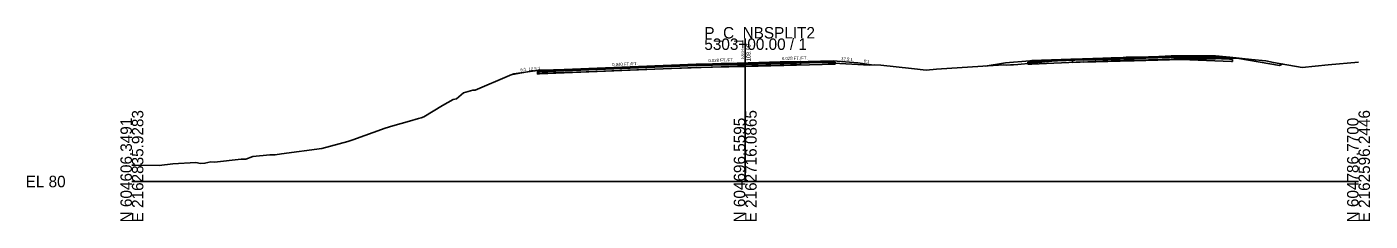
# Model space of a CAD drawing. Extents: x -26 to 1303, y -10 to 12038.
# Drawn here: x -25.7 to 302.8, y 11990.3 to 12037.8 of the extents above; entities that cross this region are included whole.
import ezdxf

# ---------------------------------------------------------------- set-up
doc = ezdxf.new("R2010")
doc.units = 0
for name, color, linetype in [('RD_GPK_XS_Cell', 7, 'Continuous'), ('RD_XS_Base', 7, 'Continuous'), ('RD_XS_ExGround', 7, 'Continuous'), ('RD_XS_ExPaveRet', 7, 'Continuous'), ('RD_XS_Greenside', 7, 'Continuous'), ('RD_XS_Pave', 7, 'Continuous'), ('RD_XS_PaveOvlay_CP', 7, 'Continuous'), ('RD_XS_TieSlope', 7, 'Continuous'), ('RD_XS_TX_Elev_EX', 7, 'Continuous'), ('RD_XS_TX_Elev_PR', 7, 'Continuous'), ('RD_XS_TX_ShdSlope', 7, 'Continuous'), ('RD_XS_TX_Slope', 7, 'Continuous')]:
    doc.layers.add(name, color=color, linetype=linetype)

msp = doc.modelspace()

# ---------------------------------------------------------------- linework, layer by layer
at = {"layer": 'RD_GPK_XS_Cell'}
for p, q in [((150, 12000), (150, 12035)), ((0, 12000), (150, 12000)), ((150, 12000), (300, 12000))]:
    msp.add_line(p, q, dxfattribs=at)
at = {"layer": 'RD_XS_Base'}
for p, q in [((138, 12028.36), (99.67, 12026.82)), ((99.67, 12026.32), (138, 12027.86)), ((150, 12028.67), (138, 12028.36)), ((138, 12028.36), (138, 12028.36)), ((138, 12027.86), (150, 12028.17)), ((138, 12027.86), (138, 12027.86)), ((150, 12028.67), (172.02, 12029.24)), ((150, 12028.17), (150, 12028.83)), ((150, 12028.83), (150, 12028.83)), ((150, 12028.83), (150, 12028.83)), ((150, 12028.83), (150, 12028.67)), ((172.02, 12028.74), (150, 12028.17)), ((150, 12028.67), (150, 12028.67)), ((150, 12028.17), (150, 12028.67)), ((150, 12028.67), (150, 12028.67)), ((150, 12028.67), (150, 12028.67)), ((150, 12028.17), (150, 12028.17)), ((171.52, 12029.23), (171.52, 12029.23)), ((172.02, 12029.24), (172.02, 12028.74)), ((172.02, 12029.21), (172.02, 12029.21)), ((219.17, 12029.21), (219.15, 12029.21)), ((219.15, 12029.21), (219.15, 12028.73)), ((219.15, 12028.73), (219.15, 12028.71)), ((219.15, 12028.71), (219.17, 12028.71)), ((219.65, 12029.23), (219.17, 12029.21)), ((219.17, 12028.71), (219.65, 12028.73)), ((220.13, 12029.25), (219.65, 12029.23)), ((219.65, 12028.73), (220.13, 12028.75)), ((232.7, 12029.75), (220.13, 12029.25)), ((220.13, 12028.75), (232.7, 12029.25)), ((244.7, 12030.05), (232.7, 12029.71)), ((232.7, 12029.21), (244.7, 12029.55)), ((244.7, 12030.06), (244.7, 12030.21)), ((244.7, 12030.21), (244.7, 12029.57)), ((244.7, 12030.05), (244.7, 12030.06)), ((245.11, 12030.06), (244.7, 12030.05)), ((244.7, 12030.05), (244.7, 12030.05)), ((244.7, 12030.05), (244.7, 12030.05)), ((244.7, 12029.57), (244.7, 12030.05)), ((244.7, 12029.57), (244.7, 12029.55)), ((244.7, 12029.55), (244.7, 12029.57)), ((244.7, 12029.55), (245.11, 12029.56)), ((256.7, 12030.39), (245.11, 12030.06)), ((245.11, 12029.56), (256.7, 12029.89)), ((268.42, 12029.92), (256.7, 12030.39)), ((256.7, 12029.89), (268.91, 12029.4)), ((268.7, 12029.91), (268.42, 12029.92)), ((269.19, 12029.89), (268.7, 12029.91)), ((268.91, 12029.4), (269.2, 12029.39)), ((269.2, 12029.89), (269.19, 12029.89)), ((269.2, 12029.4), (269.2, 12029.89)), ((269.2, 12029.39), (269.2, 12029.4)), ((99.67, 12026.82), (99.17, 12026.8)), ((99.17, 12026.8), (99.17, 12026.8)), ((99.17, 12026.8), (99.17, 12026.3)), ((99.17, 12026.3), (99.67, 12026.32)), ((99.67, 12026.82), (99.67, 12026.82)), ((99.67, 12026.32), (99.67, 12026.32))]:
    msp.add_line(p, q, dxfattribs=at)
at = {"layer": 'RD_XS_ExGround'}
msp.add_lwpolyline([(0, 12004.02), (0.8, 12004.02), (6.64, 12003.95), (10.01, 12004.29), (15.6, 12004.64), (16.74, 12004.44), (17.85, 12004.47), (19.27, 12004.8), (20.22, 12004.77), (26.73, 12005.51), (27.9, 12005.49), (29.61, 12006.12), (33.77, 12006.51), (35.07, 12006.5), (36.55, 12006.74), (46.41, 12008.11), (52.78, 12009.81), (54.05, 12010.17), (61.97, 12013.04), (63.85, 12013.65), (67.85, 12014.75), (70.1, 12015.38), (70.76, 12015.61), (71.36, 12015.86), (76, 12018.63), (78.61, 12020.1), (79.4, 12020.24), (81.13, 12021.73), (83.34, 12022.33), (83.99, 12022.34), (92.34, 12025.9), (92.53, 12025.99), (93.39, 12026.35), (99.09, 12027.16), (99.29, 12027.2), (99.41, 12027.21), (100.3, 12027.23), (108.76, 12027.48), (113.45, 12027.68), (121.26, 12027.99), (129.95, 12028.35), (134.09, 12028.49), (134.44, 12028.51), (136.77, 12028.59), (144.11, 12028.84), (148.09, 12028.99), (158.52, 12029.25), (163.52, 12029.38), (167.74, 12029.15), (168.86, 12029.09), (180.36, 12028.5), (181.59, 12028.52), (183.18, 12028.46), (190.7, 12027.63), (194.28, 12027.25), (196.82, 12027.51), (213.2, 12028.52), (213.82, 12028.5), (214.86, 12028.52), (215.64, 12028.53), (216.64, 12028.62), (230.04, 12029.91), (240.12, 12030.29), (242.47, 12030.37), (244.95, 12030.44), (245.4, 12030.45), (247.57, 12030.45), (248.77, 12030.49), (249.24, 12030.5), (249.54, 12030.51), (249.72, 12030.54), (254.85, 12030.74), (261.42, 12030.76), (265, 12030.78), (268.54, 12030.42), (273.82, 12029.87), (277.36, 12029.5), (279.22, 12029.16), (286.24, 12027.93), (292.61, 12028.53), (300, 12029.24)], dxfattribs=at)
at = {"layer": 'RD_XS_ExPaveRet'}
for points in [[(163.52, 12029.38), (163.52, 12029.38), (163.52, 12029.38), (163.52, 12028.63), (163.52, 12028.63), (158.52, 12028.5), (158.52, 12028.5), (148.09, 12028.24), (148.09, 12028.24), (144.11, 12028.09), (144.11, 12028.09), (136.77, 12027.84), (136.77, 12027.84), (134.44, 12027.76), (134.09, 12027.74), (134.09, 12027.74), (129.95, 12027.6), (129.95, 12027.6), (129.95, 12027.6), (121.26, 12027.24), (121.26, 12027.24), (113.45, 12026.93), (113.45, 12026.93), (108.76, 12026.73), (100.3, 12026.48), (100.3, 12026.48), (99.41, 12026.46), (99.29, 12026.45), (99.29, 12026.45), (99.29, 12027.2), (99.29, 12027.2), (99.29, 12027.2), (99.41, 12027.21), (100.3, 12027.23), (100.3, 12027.23), (108.76, 12027.48), (113.45, 12027.68), (113.45, 12027.68), (121.26, 12027.99), (121.26, 12027.99), (129.95, 12028.35), (129.95, 12028.35), (129.95, 12028.35), (134.09, 12028.49), (134.09, 12028.49), (134.44, 12028.51), (136.77, 12028.59), (136.77, 12028.59), (144.11, 12028.84), (144.11, 12028.84), (148.09, 12028.99), (148.09, 12028.99), (158.52, 12029.25), (158.52, 12029.25), (163.52, 12029.38)], [(158.52, 12029.25), (148.09, 12028.99), (144.11, 12028.84), (136.77, 12028.59), (134.44, 12028.51), (134.09, 12028.49), (129.95, 12028.35), (121.26, 12027.99), (113.45, 12027.68), (108.76, 12027.48), (100.3, 12027.23), (99.41, 12027.21), (99.29, 12027.2), (99.29, 12026.45), (99.41, 12026.46), (100.3, 12026.48), (108.76, 12026.73), (113.45, 12026.93), (121.26, 12027.24), (129.95, 12027.6), (134.09, 12027.74), (134.44, 12027.76), (136.77, 12027.84), (144.11, 12028.09), (148.09, 12028.24), (158.52, 12028.5), (163.52, 12028.63), (163.52, 12029.38), (158.52, 12029.25)], [(265, 12030.78), (263.03, 12030.77), (261.42, 12030.76), (255.7, 12030.74), (254.85, 12030.74), (254.19, 12030.72), (249.72, 12030.54), (249.59, 12030.52), (249.36, 12030.51), (249.32, 12030.51), (249.25, 12030.51), (249.17, 12030.5), (248.77, 12030.49), (248.61, 12030.49), (247.57, 12030.45), (246.93, 12030.45), (245.4, 12030.45), (245.08, 12030.44), (244.95, 12030.44), (243.18, 12030.39), (242.62, 12030.37), (239.98, 12030.28), (239.51, 12030.26), (237.48, 12030.19), (230.04, 12029.91), (230.04, 12029.91), (230.04, 12029.76), (230.04, 12029.16), (230.04, 12029.16), (237.48, 12029.44), (239.51, 12029.51), (239.98, 12029.53), (242.62, 12029.62), (243.18, 12029.64), (244.95, 12029.69), (245.08, 12029.69), (245.4, 12029.7), (246.93, 12029.7), (247.57, 12029.7), (248.61, 12029.74), (248.77, 12029.74), (249.17, 12029.75), (249.25, 12029.76), (249.32, 12029.76), (249.36, 12029.76), (249.59, 12029.77), (249.72, 12029.79), (254.19, 12029.97), (254.85, 12029.99), (255.7, 12029.99), (261.42, 12030.01), (263.03, 12030.02), (265, 12030.03), (265, 12030.03), (265, 12030.03), (265, 12030.61), (265, 12030.78), (265, 12030.78), (265, 12030.78)], [(265, 12030.78), (263.03, 12030.77), (261.42, 12030.76), (255.7, 12030.74), (254.85, 12030.74), (254.19, 12030.72), (249.72, 12030.54), (249.59, 12030.52), (249.36, 12030.51), (249.32, 12030.51), (249.25, 12030.51), (249.17, 12030.5), (248.77, 12030.49), (248.61, 12030.49), (247.57, 12030.45), (246.93, 12030.45), (245.4, 12030.45), (245.08, 12030.44), (244.95, 12030.44), (243.18, 12030.39), (242.62, 12030.37), (239.98, 12030.28), (239.51, 12030.26), (237.48, 12030.19), (230.04, 12029.91), (230.04, 12029.76), (230.04, 12029.16), (237.48, 12029.44), (239.51, 12029.51), (239.98, 12029.53), (242.62, 12029.62), (243.18, 12029.64), (244.95, 12029.69), (245.08, 12029.69), (245.4, 12029.7), (246.93, 12029.7), (247.57, 12029.7), (248.61, 12029.74), (248.77, 12029.74), (249.17, 12029.75), (249.25, 12029.76), (249.32, 12029.76), (249.36, 12029.76), (249.59, 12029.77), (249.72, 12029.79), (254.19, 12029.97), (254.85, 12029.99), (255.7, 12029.99), (261.42, 12030.01), (263.03, 12030.02), (265, 12030.03), (265, 12030.03), (265, 12030.61), (265, 12030.78), (265, 12030.78)]]:
    msp.add_lwpolyline(points, dxfattribs=at)
at = {"layer": 'RD_XS_Greenside'}
for p, q in [((177.52, 12029.07), (180.88, 12028.51)), ((213.65, 12029.07), (208.68, 12028.24)), ((270.7, 12030.07), (280.7, 12028.4)), ((280.7, 12028.4), (281.45, 12028.77)), ((97.67, 12026.98), (93.07, 12026.21))]:
    msp.add_line(p, q, dxfattribs=at)
at = {"layer": 'RD_XS_Pave'}
for p, q in [((138, 12028.68), (99.67, 12027.14)), ((99.67, 12026.98), (138, 12028.52)), ((138, 12028.52), (99.67, 12026.98)), ((99.67, 12026.82), (138, 12028.36)), ((150, 12028.99), (138, 12028.68)), ((138, 12028.52), (150, 12028.83)), ((150, 12028.83), (138, 12028.52)), ((138, 12028.68), (138, 12028.68)), ((138, 12028.36), (150, 12028.67)), ((138, 12028.52), (138, 12028.52)), ((138, 12028.52), (138, 12028.52)), ((138, 12028.36), (138, 12028.36)), ((171.52, 12029.55), (150, 12028.99)), ((171.52, 12029.39), (150, 12028.83)), ((150, 12028.83), (171.52, 12029.39)), ((150, 12028.67), (171.52, 12029.23)), ((150, 12028.99), (150, 12028.99)), ((150, 12028.83), (150, 12028.83)), ((150, 12028.83), (150, 12028.83)), ((150, 12028.83), (150, 12028.67)), ((150, 12028.83), (150, 12028.83)), ((150, 12028.67), (150, 12028.83)), ((150, 12028.83), (150, 12028.83)), ((150, 12028.83), (150, 12028.83)), ((150, 12028.67), (150, 12028.67)), ((150, 12028.67), (150, 12028.67)), ((171.52, 12029.39), (171.52, 12029.55)), ((171.52, 12029.55), (171.52, 12029.55)), ((171.52, 12029.23), (171.52, 12029.39)), ((171.52, 12029.39), (171.52, 12029.39)), ((220.13, 12029.57), (219.65, 12029.55)), ((219.65, 12029.55), (219.65, 12029.4)), ((220.13, 12029.41), (219.65, 12029.39)), ((219.65, 12029.39), (220.13, 12029.41)), ((219.65, 12029.4), (219.65, 12029.39)), ((219.65, 12029.39), (219.65, 12029.24)), ((219.65, 12029.23), (220.13, 12029.25)), ((219.65, 12029.24), (219.65, 12029.23)), ((229.65, 12029.95), (220.13, 12029.57)), ((232.7, 12029.91), (220.13, 12029.41)), ((220.13, 12029.41), (232.7, 12029.91)), ((220.13, 12029.25), (232.7, 12029.75)), ((232.7, 12030.03), (229.65, 12029.95)), ((244.7, 12030.37), (232.7, 12030.03)), ((244.7, 12030.21), (232.7, 12029.87)), ((232.7, 12029.87), (244.7, 12030.21)), ((232.7, 12029.71), (244.7, 12030.05)), ((245.11, 12030.38), (244.7, 12030.37)), ((245.11, 12030.22), (244.7, 12030.21)), ((244.7, 12030.21), (245.11, 12030.22)), ((244.7, 12030.06), (244.7, 12030.21)), ((244.7, 12030.21), (244.7, 12030.21)), ((244.7, 12030.21), (244.7, 12030.21)), ((244.7, 12030.21), (244.7, 12030.06)), ((244.7, 12030.05), (244.7, 12030.06)), ((244.7, 12030.06), (244.7, 12030.05)), ((244.7, 12030.05), (245.11, 12030.06)), ((244.7, 12030.05), (244.7, 12030.05)), ((244.7, 12030.05), (244.7, 12030.05)), ((256.7, 12030.7), (245.11, 12030.38)), ((256.7, 12030.55), (245.11, 12030.22)), ((245.11, 12030.22), (256.7, 12030.55)), ((245.11, 12030.06), (256.7, 12030.39)), ((268.42, 12030.24), (256.7, 12030.7)), ((268.42, 12030.08), (256.7, 12030.55)), ((256.7, 12030.55), (268.42, 12030.08)), ((256.7, 12030.39), (268.42, 12029.92)), ((268.7, 12030.22), (268.42, 12030.24)), ((268.7, 12030.07), (268.42, 12030.08)), ((268.42, 12030.08), (268.7, 12030.07)), ((268.42, 12029.92), (268.7, 12029.91)), ((268.7, 12030.07), (268.7, 12030.22)), ((268.7, 12029.91), (268.7, 12030.07)), ((268.7, 12030.07), (268.7, 12030.07)), ((268.7, 12029.91), (268.7, 12029.91)), ((99.67, 12027.14), (99.67, 12027.14)), ((99.67, 12027.14), (99.67, 12026.98)), ((99.67, 12026.98), (99.67, 12026.98)), ((99.67, 12026.98), (99.67, 12026.82))]:
    msp.add_line(p, q, dxfattribs=at)
at = {"layer": 'RD_XS_PaveOvlay_CP'}
for p, q in [((138, 12028.68), (99.67, 12027.14)), ((150, 12028.99), (138, 12028.68)), ((138, 12028.68), (138, 12028.68)), ((171.52, 12029.55), (150, 12028.99)), ((150, 12028.99), (150, 12028.99)), ((220.13, 12029.57), (219.65, 12029.55)), ((229.65, 12029.95), (220.13, 12029.57)), ((232.7, 12030.03), (229.65, 12029.95)), ((244.7, 12030.37), (232.7, 12030.03)), ((245.11, 12030.38), (244.7, 12030.37)), ((256.7, 12030.7), (245.11, 12030.38)), ((268.42, 12030.24), (256.7, 12030.7)), ((268.7, 12030.22), (268.42, 12030.24))]:
    msp.add_line(p, q, dxfattribs=at)
at = {"layer": 'RD_XS_TieSlope'}
for p, q in [((171.52, 12029.55), (177.52, 12029.07)), ((219.65, 12029.55), (213.65, 12029.07)), ((268.7, 12030.22), (270.7, 12030.07)), ((99.67, 12027.14), (97.67, 12026.98))]:
    msp.add_line(p, q, dxfattribs=at)

# ---------------------------------------------------------------- texts
at = {"layer": 'RD_GPK_XS_Cell'}
for s, p in [('P_C_NBSPLIT2', (140, 12035)), ('5303+00.00 / 1', (140, 12032.2)), ('EL 80', (-26, 11998.6))]:
    msp.add_text(s, height=2.8, dxfattribs=at).set_placement(p)
for s, p in [('N 604606.3491', (0, 11990)), ('E 2162835.9283', (2.8, 11990)), ('N 604696.5595', (150, 11990)), ('E 2162716.0865', (152.8, 11990)), ('N 604786.7700', (300, 11990)), ('E 2162596.2446', (302.8, 11990))]:
    msp.add_text(s, height=2.8, rotation=90, dxfattribs=at).set_placement(p)
at = {"layer": 'RD_XS_TX_Elev_EX'}
msp.add_text('109.04', height=0.6, rotation=90, dxfattribs=at).set_placement((149.62, 12029.92))
at = {"layer": 'RD_XS_TX_Elev_PR'}
msp.add_text('108.99', height=1, rotation=90, dxfattribs=at).set_placement((151.3, 12029.4))
at = {"layer": 'RD_XS_TX_ShdSlope'}
for rotation, p in [(4.5739, (97.06, 12027.11)), (355.4261, (173.41, 12029.71))]:
    msp.add_text('12.5:1', height=0.75, rotation=rotation, dxfattribs=at).set_placement(p)
at = {"layer": 'RD_XS_TX_Slope'}
for s, rotation, p in [('6:1', 9.4642, (95.08, 12026.91)), ('0.040 FT./FT.', 2.2906, (117.47, 12028.23)), ('0.028 FT./FT.', 1.6039, (141, 12029.21)), ('0.028 FT./FT.', 1.6039, (159, 12029.72)), ('6:1', 350.5377, (178.91, 12029.17))]:
    msp.add_text(s, height=0.75, rotation=rotation, dxfattribs=at).set_placement(p)

doc.saveas('drawing.dxf')
